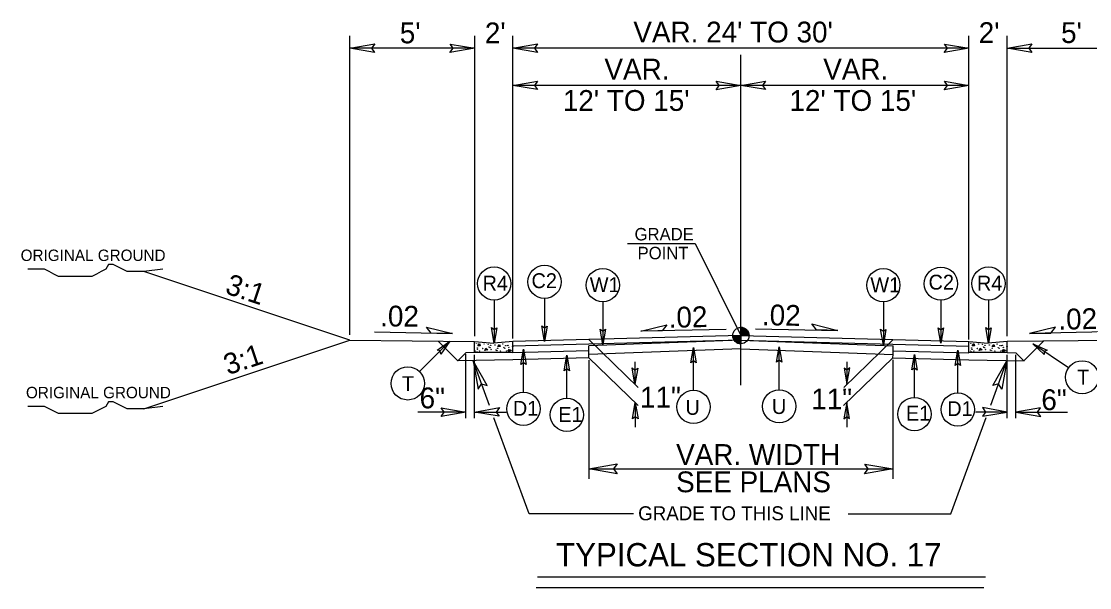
# Model space of a CAD drawing. Extents: x 957297 to 961629, y 830661 to 840840.
# Drawn here: x 959168.2 to 959568.3, y 832355.8 to 832568.1 of the extents above; entities that cross this region are included whole.
import ezdxf

# ---------------------------------------------------------------- set-up
doc = ezdxf.new("R2010")
doc.units = 0
for name, color, linetype in [('Default', 7, 'Continuous'), ('Old_Level_1', 7, 'Continuous'), ('Old_Level_11', 7, 'Continuous'), ('Old_Level_21', 7, 'Continuous'), ('Old_Level_3', 7, 'Continuous'), ('Prop CMT Pvmt Milling', 7, 'Continuous'), ('Prop Dimension Text', 7, 'Continuous'), ('Typical Curb CELL', 7, 'Continuous'), ('Typical ID Circle CELL', 7, 'Continuous'), ('Typical Terminator CELL', 7, 'Continuous'), ('Typical Text Grade Point CELL', 7, 'Continuous'), ('Typical Text ID Circle CELL', 7, 'Continuous')]:
    doc.layers.add(name, color=color, linetype=linetype)

# ---------------------------------------------------------------- blocks, each defined once
blk = doc.blocks.new('VALLEY GUTTER')
at = {"layer": 'Typical Curb CELL'}
for p, q in [((0, 0), (1, -0.083)), ((0, -0.583), (0, 0)), ((2, 0), (1, -0.083)), ((2, -0.583), (2, 0)), ((0.169, -0.231), (0.256, -0.112)), ((0.29, -0.225), (0.169, -0.231)), ((0.256, -0.112), (0.29, -0.225)), ((0.528, -0.47), (0.591, -0.355)), ((0.694, -0.43), (0.528, -0.47)), ((0.591, -0.355), (0.694, -0.43)), ((1.216, -0.275), (1.303, -0.155)), ((1.337, -0.269), (1.216, -0.275)), ((1.303, -0.155), (1.337, -0.269)), ((1.739, -0.513), (1.825, -0.393)), ((1.859, -0.507), (1.739, -0.513)), ((1.825, -0.393), (1.859, -0.507)), ((2, -0.583), (0, -0.583))]:
    blk.add_line(p, q, dxfattribs=at)
for centre in [(0.064, -0.507), (0.1, -0.102), (0.12, -0.541), (0.139, -0.34), (0.153, -0.414), (0.255, -0.5), (0.43, -0.364), (0.502, -0.131), (0.716, -0.141), (0.752, -0.294), (0.808, -0.328), (0.841, -0.202), (0.866, -0.417), (1.069, -0.188), (1.123, -0.446), (1.179, -0.48), (1.212, -0.353), (1.361, -0.49), (1.474, -0.138), (1.533, -0.316), (1.589, -0.35), (1.622, -0.223), (1.676, -0.505), (1.698, -0.225), (1.748, -0.195), (1.795, -0.31), (1.908, -0.466), (1.989, -0.271)]:
    blk.add_circle(centre, 0.00802, dxfattribs=at)

msp = doc.modelspace()

# ---------------------------------------------------------------- linework, layer by layer
at = {"layer": 'Default'}
msp.add_line((959437.72, 832431.75), (959437.72, 832555.59), dxfattribs=at)
at = {"layer": 'Old_Level_1'}
for p, q in [((959291.3, 832450.62), (959291.3, 832562.74)), ((959338.03, 832450.08), (959338.03, 832562.74)), ((959352.28, 832449.22), (959352.28, 832562.74)), ((959523.16, 832448.88), (959523.16, 832562.75)), ((959537.46, 832450.07), (959537.46, 832562.75)), ((959338.03, 832558.04), (959291.3, 832558.04)), ((959523.16, 832558.04), (959352.28, 832558.04)), ((959537.46, 832558.05), (959584.2, 832558.05)), ((959437.72, 832544.13), (959352.28, 832544.13)), ((959523.16, 832544.13), (959437.72, 832544.13)), ((959291.3, 832448.57), (959214.11, 832474.3)), ((959432.16, 832452.6), (959400.19, 832451.96)), ((959437.72, 832450.32), (959437.72, 832453.39)), ((959443.14, 832452.87), (959474, 832452.26)), ((959214.11, 832422.84), (959291.3, 832448.57)), ((959291.3, 832448.57), (959337.98, 832448.1)), ((959300.45, 832451.68), (959329.67, 832451.1)), ((959331.71, 832440.89), (959324.37, 832448.24)), ((959437.72, 832450.32), (959352.28, 832448.1)), ((959437.72, 832448.59), (959352.28, 832446.37)), ((959380.8, 832448.84), (959399.27, 832430.91)), ((959437.72, 832448.59), (959380.8, 832446.43)), ((959434.66, 832450.32), (959437.72, 832450.32)), ((959437.72, 832450.32), (959523.16, 832448.1)), ((959440.78, 832450.32), (959437.72, 832450.32)), ((959437.72, 832447.28), (959437.72, 832450.32)), ((959437.72, 832450.32), (959437.72, 832447.28)), ((959437.72, 832450.32), (959437.72, 832448.59)), ((959437.72, 832448.59), (959523.16, 832446.37)), ((959437.72, 832448.59), (959494.72, 832446.43)), ((959494.71, 832448.84), (959476.23, 832430.91)), ((959584.2, 832448.57), (959537.46, 832448.1)), ((959543.73, 832440.89), (959551.07, 832448.24)), ((959574.99, 832451.68), (959545.77, 832451.1)), ((959380.8, 832444.56), (959352.28, 832443.82)), ((959380.8, 832443.25), (959380.8, 832446.43)), ((959437.68, 832445.41), (959380.8, 832443.25)), ((959437.68, 832445.41), (959494.72, 832443.24)), ((959494.72, 832443.24), (959494.72, 832446.43)), ((959494.72, 832444.56), (959523.16, 832443.82)), ((959334.68, 832443.86), (959331.71, 832440.89)), ((959352.28, 832441.27), (959331.71, 832440.89)), ((959337.98, 832443.93), (959334.68, 832443.86)), ((959334.68, 832419.37), (959334.68, 832443.41)), ((959343.54, 832424.07), (959337.4, 832440.89)), ((959337.98, 832419.37), (959337.98, 832443.13)), ((959380.8, 832442.01), (959352.28, 832441.27)), ((959380.76, 832441.1), (959380.76, 832396.63)), ((959380.8, 832442.01), (959380.8, 832443.25)), ((959380.8, 832442.01), (959399.27, 832424.09)), ((959398.06, 832440.45), (959398.06, 832432.09)), ((959494.68, 832442.01), (959476.21, 832424.08)), ((959477.45, 832440.45), (959477.44, 832432.09)), ((959494.68, 832442.01), (959494.72, 832443.24)), ((959494.68, 832442.01), (959523.16, 832441.27)), ((959494.68, 832441.2), (959494.68, 832396.63)), ((959523.16, 832441.27), (959543.77, 832440.86)), ((959531.3, 832424.25), (959537.38, 832440.9)), ((959537.46, 832443.93), (959540.76, 832443.86)), ((959537.46, 832419.37), (959537.46, 832443.13)), ((959540.76, 832443.86), (959543.73, 832440.89)), ((959540.76, 832419.37), (959540.76, 832443.13)), ((959398.12, 832425.19), (959398.12, 832415.97)), ((959477.38, 832425.26), (959477.38, 832416.04)), ((959334.68, 832421.67), (959316.66, 832421.67)), ((959337.98, 832421.67), (959349.75, 832421.67)), ((959537.46, 832421.67), (959525.65, 832421.67)), ((959540.76, 832421.67), (959560.03, 832421.67)), ((959358.37, 832383.51), (959345.22, 832419.47)), ((959516.41, 832383.51), (959529.6, 832419.6)), ((959380.76, 832400.32), (959494.68, 832400.32)), ((959397.52, 832383.51), (959358.37, 832383.51)), ((959477.91, 832383.51), (959516.41, 832383.51)), ((959361.6, 832359.93), (959529.29, 832359.93)), ((959361.04, 832355.81), (959528.74, 832355.81))]:
    msp.add_line(p, q, dxfattribs=at)
for points in [[(959437.76, 832453.39), (959437.76, 832453.39), (959437.76, 832450.32)], [(959437.81, 832453.39), (959437.81, 832450.32)], [(959437.87, 832453.38), (959437.87, 832450.32)], [(959437.94, 832453.37), (959437.94, 832450.32)], [(959438, 832453.37), (959438, 832450.32)], [(959438.06, 832453.37), (959438.06, 832450.32)], [(959438.12, 832453.36), (959438.12, 832450.32)], [(959438.18, 832453.36), (959438.18, 832450.32)], [(959438.23, 832453.34), (959438.23, 832450.32)], [(959438.3, 832453.34), (959438.3, 832450.32)], [(959438.36, 832453.32), (959438.36, 832450.32)], [(959438.42, 832453.31), (959438.42, 832450.32)], [(959438.49, 832453.28), (959438.49, 832450.32)], [(959438.55, 832453.27), (959438.55, 832450.32)], [(959438.61, 832453.25), (959438.61, 832450.32)], [(959438.67, 832453.23), (959438.67, 832450.32)], [(959438.74, 832453.21), (959438.73, 832450.32)], [(959438.79, 832453.19), (959438.79, 832450.32)], [(959438.85, 832453.18), (959438.85, 832450.32)], [(959438.92, 832453.15), (959438.92, 832450.32)], [(959438.98, 832453.12), (959438.98, 832450.32)], [(959439.04, 832453.09), (959439.04, 832450.32)], [(959439.09, 832453.06), (959439.09, 832450.32)], [(959439.15, 832453.04), (959439.15, 832450.32)], [(959439.21, 832453), (959439.21, 832450.32)], [(959439.28, 832452.96), (959439.28, 832450.32)], [(959439.34, 832452.93), (959439.34, 832450.32)], [(959439.4, 832452.88), (959439.4, 832450.32)], [(959439.47, 832452.83), (959439.47, 832450.32)], [(959439.52, 832452.8), (959439.52, 832450.32)], [(959439.59, 832452.75), (959439.59, 832450.32)], [(959439.65, 832452.71), (959439.65, 832450.32)], [(959439.71, 832452.66), (959439.71, 832450.32)], [(959439.77, 832452.6), (959439.77, 832450.32)], [(959439.83, 832452.54), (959439.83, 832450.32)], [(959439.9, 832452.48), (959439.9, 832450.32)], [(959439.95, 832452.42), (959439.95, 832450.32)], [(959440.01, 832452.36), (959440.01, 832450.32)], [(959440.07, 832452.29), (959440.07, 832450.32)], [(959440.13, 832452.2), (959440.13, 832450.32)], [(959440.2, 832452.12), (959440.2, 832450.32)], [(959440.26, 832452.04), (959440.26, 832450.32)], [(959434.68, 832450.32), (959434.68, 832450)], [(959434.74, 832450.32), (959434.74, 832449.64)], [(959434.8, 832450.32), (959434.8, 832449.42)], [(959434.86, 832450.32), (959434.86, 832449.23)], [(959434.93, 832450.32), (959434.93, 832449.09)], [(959434.99, 832450.32), (959434.99, 832448.96)], [(959435.05, 832450.32), (959435.05, 832448.85)], [(959435.11, 832450.32), (959435.11, 832448.73)], [(959435.17, 832450.32), (959435.17, 832448.65)], [(959435.23, 832450.32), (959435.23, 832448.56)], [(959435.3, 832450.32), (959435.3, 832448.47)], [(959435.36, 832450.32), (959435.36, 832448.4)], [(959435.42, 832450.32), (959435.42, 832448.33)], [(959435.47, 832450.32), (959435.47, 832448.25)], [(959435.53, 832450.32), (959435.53, 832448.19)], [(959435.6, 832450.32), (959435.6, 832448.13)], [(959435.66, 832450.32), (959435.66, 832448.08)], [(959435.72, 832450.32), (959435.72, 832448.02)], [(959435.78, 832450.32), (959435.78, 832447.97)], [(959435.85, 832450.32), (959435.85, 832447.91)], [(959435.9, 832450.32), (959435.9, 832447.88)], [(959435.96, 832450.32), (959435.96, 832447.83)], [(959436.02, 832450.32), (959436.02, 832447.79)], [(959436.09, 832450.32), (959436.09, 832447.74)], [(959436.15, 832450.32), (959436.15, 832447.7)], [(959436.21, 832450.32), (959436.21, 832447.66)], [(959436.28, 832450.32), (959436.28, 832447.63)], [(959436.33, 832450.32), (959436.33, 832447.62)], [(959436.39, 832450.32), (959436.39, 832447.58)], [(959436.46, 832450.32), (959436.46, 832447.54)], [(959436.52, 832450.32), (959436.52, 832447.53)], [(959436.58, 832450.32), (959436.58, 832447.49)], [(959436.64, 832450.32), (959436.64, 832447.47)], [(959436.7, 832450.32), (959436.7, 832447.45)], [(959436.75, 832450.32), (959436.75, 832447.43)], [(959436.82, 832450.32), (959436.82, 832447.41)], [(959436.88, 832450.32), (959436.88, 832447.39)], [(959436.94, 832450.32), (959436.94, 832447.37)], [(959437, 832450.32), (959437, 832447.37)], [(959437.07, 832450.32), (959437.07, 832447.34)], [(959437.13, 832450.32), (959437.13, 832447.33)], [(959437.19, 832450.32), (959437.19, 832447.33)], [(959437.25, 832450.32), (959437.25, 832447.31)], [(959437.31, 832450.32), (959437.31, 832447.29)], [(959437.38, 832450.32), (959437.38, 832447.29)], [(959437.44, 832450.32), (959437.44, 832447.29)], [(959437.5, 832450.32), (959437.5, 832447.28)], [(959437.56, 832450.32), (959437.56, 832447.28)], [(959437.61, 832450.32), (959437.61, 832447.28)], [(959437.67, 832450.32), (959437.67, 832447.28), (959437.67, 832447.28)], [(959440.32, 832451.95), (959440.32, 832450.32)], [(959440.38, 832451.84), (959440.38, 832450.32)], [(959440.44, 832451.73), (959440.44, 832450.32)], [(959440.5, 832451.59), (959440.5, 832450.32)], [(959440.57, 832451.44), (959440.57, 832450.32)], [(959440.63, 832451.29), (959440.63, 832450.32)], [(959440.69, 832451.07), (959440.69, 832450.32)], [(959440.75, 832450.77), (959440.75, 832450.32)]]:
    msp.add_lwpolyline(points, dxfattribs=at)
msp.add_circle((959437.72, 832450.33), 3.06, dxfattribs=at)
for start, end in [(359.9905, 89.9905), (179.9905, 269.9905)]:
    msp.add_arc((959437.72, 832450.33), 3.06, start, end, dxfattribs=at)
at = {"layer": 'Old_Level_11'}
for p, q in [((959321.66, 832451.26), (959319.93, 832453.51)), ((959319.93, 832453.51), (959329.67, 832451.1)), ((959400.19, 832451.96), (959409.94, 832454.38)), ((959408.21, 832452.12), (959400.19, 832451.96)), ((959409.94, 832454.38), (959408.21, 832452.12)), ((959465.99, 832452.42), (959464.26, 832454.67)), ((959464.26, 832454.67), (959474, 832452.26)), ((959474, 832452.26), (959465.99, 832452.42)), ((959555.51, 832453.51), (959545.77, 832451.1)), ((959553.77, 832451.26), (959555.51, 832453.51)), ((959329.67, 832451.1), (959321.66, 832451.26)), ((959545.77, 832451.1), (959553.77, 832451.26))]:
    msp.add_line(p, q, dxfattribs=at)
for points in [[(959342.74, 832431.58), (959337.4, 832440.89), (959339.28, 832430.26), (959340.58, 832432.17)], [(959532.04, 832431.6), (959537.38, 832440.9), (959535.5, 832430.28), (959534.2, 832432.19)], [(959391.33, 832398.5), (959380.76, 832400.32), (959391.38, 832402.2), (959390.04, 832400.32)], [(959484.11, 832402.15), (959494.68, 832400.32), (959484.05, 832398.45), (959485.41, 832400.32)]]:
    msp.add_lwpolyline(points, close=True, dxfattribs=at)
at = {"layer": 'Old_Level_21'}
for points in [[(959221.2, 832475.18), (959214.11, 832474.3), (959212.33, 832474.3), (959209.67, 832474.3), (959207.9, 832474.3), (959206.13, 832475.18), (959204.35, 832476.08), (959202.58, 832476.96), (959200.8, 832476.96), (959199.91, 832475.18), (959198.15, 832474.3), (959196.37, 832473.4), (959194.6, 832472.53), (959192.82, 832472.53), (959191.05, 832472.53), (959189.27, 832472.53), (959187.5, 832472.53), (959185.73, 832472.53), (959183.96, 832472.53), (959182.18, 832472.53), (959180.41, 832473.4), (959178.64, 832474.3), (959176.87, 832475.18), (959174.2, 832475.18), (959172.43, 832475.18), (959170.65, 832475.18)], [(959221.2, 832423.72), (959214.11, 832422.84), (959212.33, 832422.84), (959209.67, 832422.84), (959207.9, 832422.84), (959206.13, 832423.72), (959204.35, 832424.61), (959202.58, 832425.49), (959200.8, 832425.49), (959199.91, 832423.72), (959198.15, 832422.84), (959196.37, 832421.94), (959194.6, 832421.07), (959192.82, 832421.07), (959191.05, 832421.07), (959189.27, 832421.07), (959187.5, 832421.07), (959185.73, 832421.07), (959183.96, 832421.07), (959182.18, 832421.07), (959180.41, 832421.94), (959178.64, 832422.84), (959176.87, 832423.72), (959174.2, 832423.72), (959172.43, 832423.72), (959170.65, 832423.72)]]:
    msp.add_lwpolyline(points, dxfattribs=at)
at = {"layer": 'Typical ID Circle CELL'}
for p, q in [((959364.18, 832464.24), (959364.18, 832448.15)), ((959345.3, 832463.61), (959345.3, 832447.52)), ((959385.98, 832463.01), (959385.98, 832446.92)), ((959491.08, 832462.96), (959491.08, 832446.88)), ((959512.65, 832463.55), (959512.65, 832447.47)), ((959530.49, 832463.61), (959530.49, 832447.52)), ((959317.34, 832436.8), (959328.72, 832448.18)), ((959356.28, 832429.13), (959356.28, 832445.21)), ((959420, 832429.79), (959420, 832445.88)), ((959452.08, 832430.02), (959452.08, 832446.11)), ((959518.95, 832428.82), (959518.95, 832444.91)), ((959560.42, 832438.19), (959547.13, 832447.27)), ((959372.54, 832426.83), (959372.54, 832442.92)), ((959502.71, 832427.12), (959502.71, 832443.21))]:
    msp.add_line(p, q, dxfattribs=at)
for centre in [(959345.3, 832469.83), (959364.18, 832470.46), (959530.49, 832469.83), (959385.98, 832469.24), (959491.08, 832469.19), (959512.65, 832469.78), (959565.56, 832434.68), (959312.94, 832432.4), (959356.28, 832422.9), (959420, 832423.57), (959452.08, 832423.8), (959518.95, 832422.6), (959372.54, 832420.6), (959502.71, 832420.9)]:
    msp.add_circle(centre, 6.23, dxfattribs=at)
at = {"layer": 'Typical Terminator CELL'}
for points in [[(959300.52, 832556.46), (959291.3, 832558.04), (959300.57, 832559.68), (959299.39, 832558.04)], [(959328.81, 832559.63), (959338.04, 832558.04), (959328.76, 832556.41), (959329.94, 832558.04)], [(959361.5, 832556.46), (959352.27, 832558.04), (959361.55, 832559.68), (959360.37, 832558.04)], [(959513.93, 832559.63), (959523.16, 832558.04), (959513.88, 832556.41), (959515.06, 832558.04)], [(959546.65, 832556.46), (959537.42, 832558.05), (959546.7, 832559.69), (959545.52, 832558.05)], [(959361.5, 832542.55), (959352.28, 832544.13), (959361.55, 832545.77), (959360.37, 832544.13)], [(959428.5, 832545.72), (959437.72, 832544.13), (959428.44, 832542.5), (959429.62, 832544.13)], [(959446.94, 832542.55), (959437.72, 832544.13), (959446.99, 832545.77), (959445.81, 832544.13)], [(959513.93, 832545.72), (959523.16, 832544.13), (959513.88, 832542.49), (959515.06, 832544.13)], [(959346.3, 832453.29), (959345.3, 832447.52), (959344.28, 832453.32), (959345.3, 832452.58)], [(959365.18, 832453.91), (959364.18, 832448.15), (959363.16, 832453.94), (959364.18, 832453.21)], [(959386.98, 832452.69), (959385.98, 832446.92), (959384.96, 832452.72), (959385.98, 832451.98)], [(959492.07, 832452.64), (959491.08, 832446.88), (959490.06, 832452.67), (959491.08, 832451.94)], [(959513.64, 832453.23), (959512.65, 832447.47), (959511.63, 832453.26), (959512.65, 832452.53)], [(959531.48, 832453.29), (959530.49, 832447.52), (959529.46, 832453.32), (959530.49, 832452.58)], [(959323.94, 832444.81), (959328.72, 832448.18), (959325.35, 832443.36), (959325.14, 832444.6)], [(959355.29, 832439.45), (959356.28, 832445.21), (959357.3, 832439.42), (959356.28, 832440.15)], [(959419.01, 832440.12), (959420, 832445.88), (959421.03, 832440.09), (959420, 832440.82)], [(959451.08, 832440.35), (959452.08, 832446.11), (959453.1, 832440.31), (959452.08, 832441.05)], [(959517.96, 832439.15), (959518.95, 832444.91), (959519.97, 832439.11), (959518.95, 832439.85)], [(959551.33, 832443.19), (959547.13, 832447.27), (959552.5, 832444.84), (959551.31, 832444.41)], [(959371.54, 832437.15), (959372.54, 832442.92), (959373.56, 832437.12), (959372.54, 832437.86)], [(959501.72, 832437.44), (959502.71, 832443.21), (959503.74, 832437.41), (959502.71, 832438.15)], [(959399.1, 832438.15), (959398.06, 832432.09), (959396.98, 832438.19), (959398.06, 832437.41)], [(959476.4, 832438.15), (959477.44, 832432.09), (959478.52, 832438.19), (959477.44, 832437.41)], [(959397.08, 832419.12), (959398.12, 832425.19), (959399.2, 832419.09), (959398.12, 832419.86)], [(959478.42, 832419.2), (959477.38, 832425.26), (959476.3, 832419.16), (959477.38, 832419.94)], [(959325.46, 832423.26), (959334.68, 832421.67), (959325.4, 832420.03), (959326.58, 832421.67)], [(959347.2, 832420.08), (959337.98, 832421.67), (959347.25, 832423.31), (959346.07, 832421.67)], [(959528.24, 832420.08), (959537.46, 832421.67), (959528.18, 832423.31), (959529.36, 832421.67)], [(959549.98, 832423.26), (959540.76, 832421.67), (959550.03, 832420.03), (959548.85, 832421.67)]]:
    msp.add_lwpolyline(points, close=True, dxfattribs=at)
at = {"layer": 'Typical Text Grade Point CELL'}
for p, q in [((959395.28, 832484.89), (959420.61, 832484.89)), ((959420.61, 832484.89), (959437.72, 832450.32))]:
    msp.add_line(p, q, dxfattribs=at)

# ---------------------------------------------------------------- block references
at = {"layer": 'Prop CMT Pvmt Milling', "xscale": 7.148915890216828, "yscale": 7.148915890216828}
for p in [(959337.98, 832448.1), (959523.16, 832448.1)]:
    msp.add_blockref('VALLEY GUTTER', p, dxfattribs=at)

# ---------------------------------------------------------------- texts
at = {"layer": 'Old_Level_1'}
for s, height, p in [("VAR. 24' TO 30'", 7.8009, (959397.45, 832560.23)), ("5'", 7.801, (959309.96, 832559.91)), ("2'", 7.801, (959341.82, 832559.91)), ("2'", 7.801, (959526.81, 832560.01)), ("5'", 7.801, (959557.65, 832560.01)), ('VAR. ', 7.801, (959386.62, 832546.32)), ('VAR. ', 7.801, (959468.59, 832546.32)), ("12' TO 15'", 7.801, (959371.03, 832534.57)), ("12' TO 15'", 7.801, (959455.92, 832534.57)), ('VAR. WIDTH', 7.801, (959413.47, 832401.81)), ('SEE PLANS', 7.801, (959413.47, 832391.58)), ('GRADE TO THIS LINE', 5.2473, (959399.24, 832381.07)), ('TYPICAL SECTION NO. 17', 8.7513, (959368.5, 832363.78))]:
    msp.add_text(s, height=height, dxfattribs=at).set_placement(p)
at = {"layer": 'Old_Level_11'}
for s, height, p in [('GRADE', 4.671, (959397.89, 832486)), ('POINT', 4.671, (959399.02, 832478.93)), ('11"', 7.801, (959399.94, 832423.32)), ('11"', 7.801, (959464.07, 832422.64))]:
    msp.add_text(s, height=height, dxfattribs=at).set_placement(p)
at = {"layer": 'Old_Level_21'}
for p in [(959167.95, 832478.29), (959169.94, 832426.83)]:
    msp.add_text('ORIGINAL GROUND', height=4.2722, dxfattribs=at).set_placement(p)
at = {"layer": 'Old_Level_3'}
for s, rotation, p in [('3:1', 341.5652, (959244.14, 832466.26)), ('.02', 359.4336, (959302.58, 832453.78)), ('3:1', 18.4348, (959245.56, 832435.44))]:
    msp.add_text(s, height=7.801, rotation=rotation, dxfattribs=at).set_placement(p)
at = {"layer": 'Prop Dimension Text'}
for s, rotation, p in [('.02', 1.1839, (959410.76, 832453.23)), ('.02', 358.8533, (959445.55, 832454.23)), ('.02', 1.1839, (959556.72, 832452.52)), ('6"', 0, (959317.39, 832423.04)), ('6"', 0, (959550.26, 832422.38))]:
    msp.add_text(s, height=7.801, rotation=rotation, dxfattribs=at).set_placement(p)
at = {"layer": 'Typical Text ID Circle CELL'}
for s, height, p in [('R4', 5.572, (959340.96, 832467.2)), ('C2', 5.572, (959359.29, 832468.12)), ('W1', 5.572, (959381.11, 832466.61)), ('W1', 5.572, (959486.21, 832466.56)), ('C2', 5.572, (959508.01, 832467.57)), ('R4', 5.572, (959526.14, 832467.2)), ('D1', 5.572, (959352.32, 832420.27)), ('U', 5.57, (959416.97, 832420.62)), ('U', 5.57, (959449.34, 832420.93)), ('E1', 5.572, (959499.54, 832418.43)), ('D1', 5.572, (959515.02, 832420.14)), ('E1', 5.572, (959369.33, 832417.97))]:
    msp.add_text(s, height=height, dxfattribs=at).set_placement(p)
for p in [(959563.65, 832431.92), (959310.76, 832429.53)]:
    msp.add_text('T', height=5.57, rotation=360, dxfattribs=at).set_placement(p)

doc.saveas('drawing.dxf')
